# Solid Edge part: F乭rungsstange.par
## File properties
Username: bmolnar
Dokumentum tartalom típus: 0
Author: bmolnar
Last saved by: bmolnar
Revision: 78
Sűrűség: 0,000 kg/m^3
Pontosság: 0,990
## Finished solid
Body 1: solid body, 8 faces, 7 edges, 5 vertices.
  Faces by surface: cone 4, cylinder 2, plane 2
  Edges by curve: circle 7
Bounding box of the edges (mm): 10.000 x 10.000 x 77.000, from (-5, -5, -43.5) to (5, 5, 33.5).
Cylindrical faces by radius (mm): R2.4585 x1, R5 x1
Conical faces (half-angle, radius in mm at the cone's reference point): 45 deg R2.7085 x1, 45 deg R4.5 x1, 45 deg R4.9 x1, 59 deg R1.2292 x1
Planar faces by outward normal: +z 1, -z 1
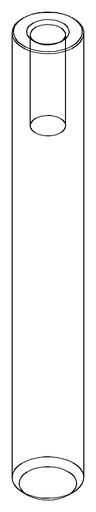
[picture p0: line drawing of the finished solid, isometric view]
